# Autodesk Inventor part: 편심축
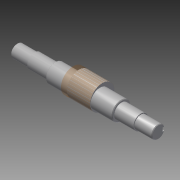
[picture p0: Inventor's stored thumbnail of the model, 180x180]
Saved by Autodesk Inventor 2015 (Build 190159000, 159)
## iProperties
Created: 2015-10
Part Number: 편심축
Document SubType Name: Modeling
Designer: mdu
Density: 7.86 g/cm^3
Material: 강철, 연강
Mass: 1327.93 g
Surface Area: 248.524 cm^2
Volume: 168.948 cm^3
Appearance: 강철
Author: mdu
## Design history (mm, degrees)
sketch "스케치1"
  geometry: L1 (-20.5, -41.331)-(-20.5, 32.669) reference; L2 (7.5, -30.031)-(7.5, 21.369) reference; L3 (135.5, -30.331)-(135.5, 21.669) reference; L4 (121.5, 21.369)-(121.5, -30.031) reference; L5 (184.5, -4.331)-(-57.5, -4.331); L6 (184.5, -4.331)-(184.5, 6.669); L7 (154.5, 8.169)-(121.5, 8.169); L8 (121.5, 8.169)-(121.5, 11.669); L9 (121.5, 11.669)-(7.5, 11.669); L10 (7.5, 11.669)-(7.5, 8.169); L11 (7.5, 8.169)-(-27.5, 8.169); L12 (-27.5, 8.169)-(-27.5, 6.669); L13 (-27.5, 6.669)-(-57.5, 6.669); L14 (-57.5, 6.669)-(-57.5, -4.331); L15 (154.5, 8.169)-(154.5, 6.669); L16 (154.5, 6.669)-(184.5, 6.669); C1 r 32.5 at (64.5, -4.331) reference; 1 further point
  constraints: 24 end point, 8 perpendicular, 5 point on line, 3 parallel, 2 collinear
  dimensions: "d1" = 25 diameter of L11 L5; "d2" = 32 diameter of L9 L5; "d3" = 22 diameter of L13 L5; "d4" = 35 distance of L10.end L11.end; "d5" = 30 distance of L12.end L13.end; "d15" = 33 distance of L7.start L7.end; "d26" = 30 distance of L15.end L6.end
revolve "회전1" sketch "스케치1" stored, may be unused: angle "d6" = 90 deg
node "작업 평면1"
sketch "스케치2"
  geometry: C1 r 16 at (0, 0) reference; C2 r 16 at (0, 0) reference; C3 r 20.75 at (0, 4); C4 r 16 at (0, 0) reference; C5 r 16 at (0, 0) reference; 1 further point
  constraints: 1 centre point, 1 vertical alignment
  dimensions: "d8" = 41.5 diameter of C3; "d25" = 4 distance of C3.centre C1.centre
extrude "돌출1" join sketch "스케치2" stored distance "d9" = 40; taper "d10" = 0 deg
chamfer "모따기1" distance "d11" = 1; stored, may be unused: second distance "d12" = 2, angle "d13" = 45 deg
node "작업 평면2"
sketch "스케치3"
  geometry: L1 (-15, -10)-(-15, 10) reference; L2 (-15, 3)-(0, 3); L3 (0, -3)-(-15, -3); A1 r 3 centre (0, 0) between (0, -3) and (0, 3); 2 further points
  constraints: 4 end point, 2 perpendicular, 2 point on circle, 2 point on line, 2 tangent, 1 centre point, 1 horizontal alignment, 1 midpoint
  dimensions: "d16" = 18 dimension on A1 L1; "d17" = 6 distance between parallel lines of L3 L2
extrude "돌출2" cut sketch "스케치3" distance "d18" = 3.5; taper "d19" = 0 deg
node "작업 평면3"
sketch "스케치5"
  geometry: C1 r 20.75 at (0, 0) reference; 1 further point
feature "돌출 곡면1" sketch "스케치5" dims "d27" = 50, "d28" = 0
node "솔리드1"
mirror "대칭1"
node "참조1"
node "참조2"
node "참조3"
node "참조4"
node "참조5"
node "투영된 루프1"
node "곡면1"
